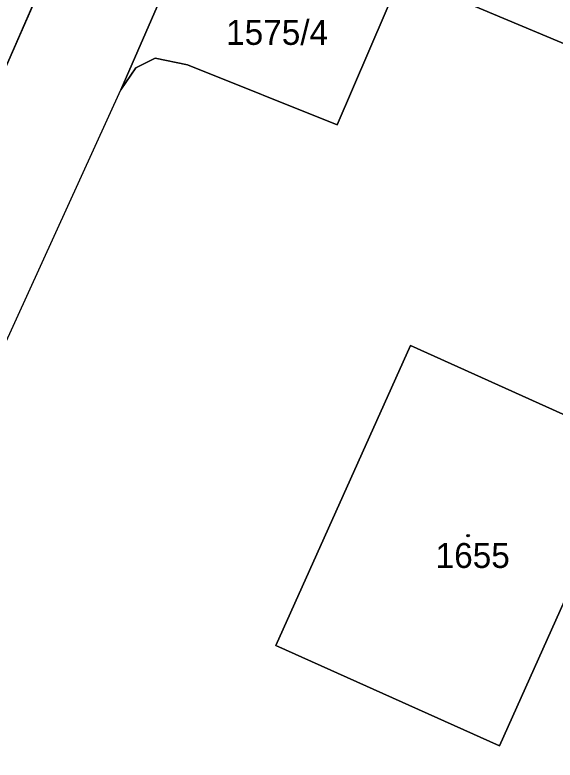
# Model space of a CAD drawing. Extents: x -596024 to -594475, y -1163820 to -1161957.
# Drawn here: x -595695.5 to -595658.7, y -1162105.4 to -1162054.6 of the extents above; entities that cross this region are included whole.
import ezdxf

# ---------------------------------------------------------------- set-up
doc = ezdxf.new("R2010")
doc.units = 0
for name, color, linetype in [('Level 1', 7, 'Continuous'), ('Level 4', 7, 'Continuous'), ('Level 5', 7, 'Continuous'), ('Level 60', 7, 'Continuous'), ('Vrstva 60', 7, 'Continuous')]:
    doc.layers.add(name, color=color, linetype=linetype)

msp = doc.modelspace()

# ---------------------------------------------------------------- linework, layer by layer
at = {"layer": 'Level 1'}
msp.add_line((-595700.42, -1162067.92), (-595651.683, -1161956.88), dxfattribs=at)
for points in [[(-595682.95, -1162047.47), (-595688.29, -1162059.74)], [(-595669.16, -1162051.9), (-595666.53, -1162053.03), (-595651.98, -1162059.14), (-595650.49, -1162054.85), (-595667.27, -1162047.5)], [(-595669.16, -1162051.9), (-595673.56, -1162062.13), (-595683.76, -1162058.04), (-595685.95, -1162057.58), (-595687.27, -1162058.23), (-595688.29, -1162059.74)], [(-595717.11, -1162129.24), (-595707.38, -1162106.85), (-595708.77, -1162106.24), (-595707.38, -1162103.08), (-595698.23, -1162081.48), (-595688.29, -1162059.74)], [(-595677.73, -1162097.6), (-595668.55, -1162077.17), (-595653.32, -1162084.01), (-595662.49, -1162104.44), (-595677.73, -1162097.6)]]:
    msp.add_lwpolyline(points, dxfattribs=at)
at = {"layer": 'Level 5'}
for radius in [0.09, 0.0521]:
    msp.add_circle((-595664.63, -1162090.12), radius, dxfattribs=at)
at = {"layer": 'Level 60'}
for points in [[(-595698.23, -1162081.48), (-595688.29, -1162059.74), (-595687.27, -1162058.23), (-595685.95, -1162057.58), (-595683.76, -1162058.04), (-595673.56, -1162062.13), (-595669.16, -1162051.9), (-595666.53, -1162053.03), (-595651.98, -1162059.14), (-595650.49, -1162054.85), (-595667.27, -1162047.5), (-595664.46, -1162040.96), (-595663.57, -1162041.38), (-595662.76, -1162040.03), (-595661.92, -1162040.41), (-595661.68, -1162039.89), (-595653.01, -1162043.65), (-595648.38, -1162045.78), (-595646.62, -1162046.56), (-595605.47, -1162064.69), (-595636.59, -1162139.13), (-595651.51, -1162132.01), (-595692.37, -1162113.74), (-595703.38, -1162138.38)], [(-595673.56, -1162062.13), (-595683.76, -1162058.04), (-595685.95, -1162057.58), (-595687.27, -1162058.23), (-595688.29, -1162059.74), (-595682.95, -1162047.47)], [(-595675.7, -1162050.89), (-595675.04, -1162049.39), (-595669.16, -1162051.9), (-595673.56, -1162062.13)]]:
    msp.add_lwpolyline(points, dxfattribs=at)
for points in [[(-595650.49, -1162054.85), (-595651.98, -1162059.14), (-595666.53, -1162053.03), (-595669.16, -1162051.9), (-595675.04, -1162049.39), (-595673.08, -1162044.96), (-595667.27, -1162047.5)], [(-595668.55, -1162077.17), (-595677.73, -1162097.6), (-595662.49, -1162104.44), (-595653.32, -1162084.01)], [(-595677.73, -1162097.6), (-595668.55, -1162077.17), (-595653.32, -1162084.01), (-595662.49, -1162104.44)]]:
    msp.add_lwpolyline(points, close=True, dxfattribs=at)
at = {"layer": 'Vrstva 60'}
msp.add_lwpolyline([(-595642.928, -1161956.88), (-595651.683, -1161956.88), (-595700.42, -1162067.92), (-595714.28, -1162100.65), (-595763.48, -1162212.38), (-595762.1, -1162212.98), (-595755.16, -1162216.01), (-595739.48, -1162180.64), (-595719.28, -1162134.23), (-595717.11, -1162129.24), (-595707.38, -1162106.85), (-595708.77, -1162106.24), (-595707.38, -1162103.08), (-595698.23, -1162081.48), (-595688.29, -1162059.74), (-595682.95, -1162047.47), (-595655.76, -1161985.63), (-595650.46, -1161973.92)], close=True, dxfattribs=at)
msp.add_lwpolyline([(-595700.42, -1162067.92), (-595651.683, -1161956.88), (-595656.438, -1161956.88), (-595660.93, -1161968.65), (-595660.82, -1161968.69), (-595660.93, -1161968.99), (-595661.27, -1161968.87), (-595661.23, -1161968.75), (-595663.18, -1161968.04), (-595663.3, -1161968.36), (-595663.41, -1161968.31), (-595669.72, -1161984.93), (-595676.15, -1162001.88), (-595682.49, -1162018.59), (-595682.38, -1162018.63), (-595682.49, -1162018.93), (-595682.83, -1162018.81), (-595682.79, -1162018.7), (-595684.7, -1162018.03), (-595684.82, -1162018.35), (-595684.93, -1162018.31), (-595691.18, -1162035.02), (-595697.57, -1162052.09)], dxfattribs=at)

# ---------------------------------------------------------------- texts
at = {"layer": 'Level 4'}
for s, p in [('1575/4', (-595681.12, -1162056.67)), ('1655', (-595666.84, -1162092.32))]:
    msp.add_text(s, height=1.7, dxfattribs=at).set_placement(p)

doc.saveas('drawing.dxf')
